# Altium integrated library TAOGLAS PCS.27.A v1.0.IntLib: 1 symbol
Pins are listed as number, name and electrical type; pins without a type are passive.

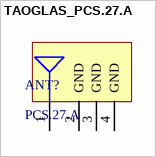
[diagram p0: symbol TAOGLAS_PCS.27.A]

## TAOGLAS_PCS.27.A
designator ANT?, comment PCS.27.A
Wi-Fi 2.4/5.8/7.125GHz FR4 PIFA Antenna with SMD 12*5*3mm; ComponentLibStatus: Created; MFG: Taoglas; Temp_High: +85C; Temp_Low: -40C
footprint TAOGLAS_PCS.27.A (Wi-Fi 2.4/5.8/7.125GHz FR4 PIFA Antenna with SMD 12*5*3mm)
pins: 1 RF FEED, 2 GND, 3 GND, 4 GND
